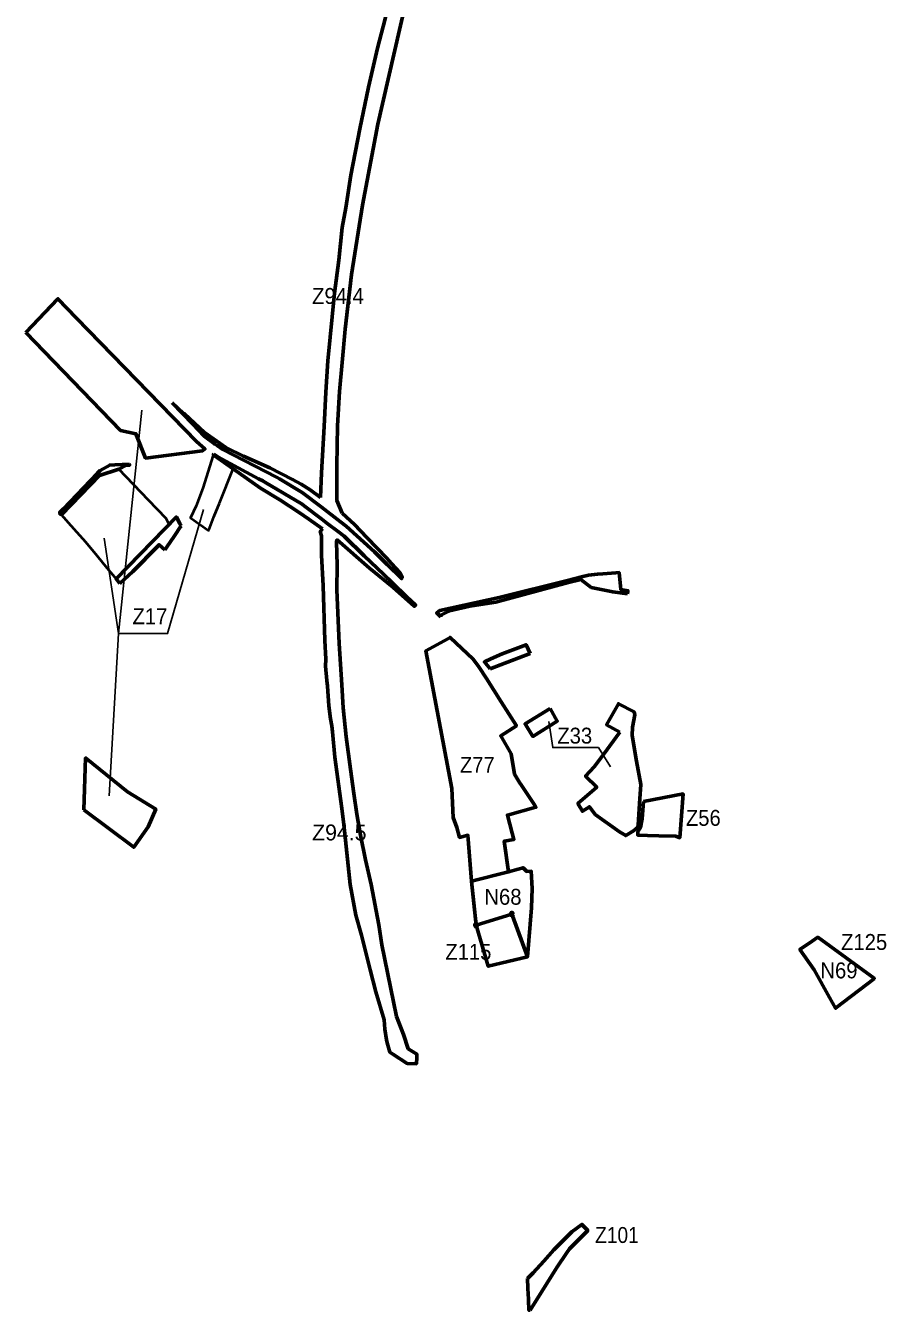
# Model space of a CAD drawing. Extents: x -650277 to -643425, y -1073980 to -1066720.
# Drawn here: x -645817 to -644519, y -1073665 to -1071727 of the extents above; entities that cross this region are included whole.
import ezdxf

# ---------------------------------------------------------------- set-up
doc = ezdxf.new("R2010")
doc.units = 0
doc.header["$LTSCALE"] = 9.6
doc.header["$PDMODE"] = 32
doc.header["$PDSIZE"] = 4.8
for name, color, linetype, lineweight in [('1', 7, 'Continuous', 60), ('15', 7, 'Continuous', 60), ('2', 7, 'Continuous', 40), ('3', 7, 'Continuous', 60), ('42', 7, 'Continuous', 60), ('59', 7, 'Continuous', 25), ('60', 7, 'Continuous', 60), ('63', 7, 'Continuous', 25), ('9', 7, 'Continuous', 60)]:
    doc.layers.add(name, color=color, linetype=linetype, lineweight=lineweight)

msp = doc.modelspace()

# ---------------------------------------------------------------- linework, layer by layer
at = {"layer": '1'}
for points in [[(-645817.219, -1072189.975), (-645768.649, -1072139.283), (-645740.45, -1072168.23), (-645559.34, -1072354.42), (-645546.82, -1072365.72), (-645550.41, -1072368.47), (-645636.37, -1072379.57), (-645650.78, -1072342.73), (-645674, -1072338), (-645789.298, -1072218.833)], [(-645729.36, -1072909.65), (-645654.16, -1072966.3), (-645632.23, -1072935.28), (-645620.92, -1072908.65), (-645663.52, -1072882.58), (-645726.9, -1072831.5)], [(-644536.62, -1073164.33), (-644536.62, -1073164.33), (-644622.03, -1073101.88), (-644622.03, -1073101.88), (-644630.58, -1073107.78), (-644648.95, -1073120.47), (-644627.53, -1073151.26), (-644604.13, -1073193), (-644595.18, -1073208.98)]]:
    msp.add_lwpolyline(points, close=True, dxfattribs=at)
at = {"layer": '15'}
for points in [[(-645708.94, -1072402.11), (-645760.02, -1072455.94), (-645765.95, -1072462.03), (-645763.06, -1072465.26)], [(-645763.06, -1072465.26), (-645706.039, -1072405.769), (-645676.53, -1072396.16)], [(-645661.3, -1072388.74), (-645682.59, -1072389.76), (-645690.37, -1072390.13), (-645705, -1072398.19), (-645708.94, -1072402.11)], [(-645676.53, -1072396.16), (-645676.53, -1072396.16), (-645665.32, -1072390.32), (-645660.16, -1072389.95), (-645661.3, -1072388.74)], [(-645582.84, -1072481.71), (-645584.46, -1072478.58), (-645589.862, -1072468.109), (-645680.87, -1072561.42), (-645675.13, -1072568.36)], [(-645607.07, -1072517.61), (-645605.95, -1072515.95), (-645604.82, -1072514.3), (-645592.9, -1072496.52), (-645583.13, -1072482.13), (-645582.84, -1072481.71)], [(-645675.13, -1072568.36), (-645655.65, -1072550.62), (-645617.87, -1072512.12), (-645615.95, -1072510.16), (-645607.07, -1072517.61)], [(-644926.81, -1072552.51), (-644946.57, -1072554.22), (-644954.57, -1072554.43), (-644967.97, -1072556.17), (-644978.56, -1072558.74), (-644999.72, -1072564.24), (-645102.73, -1072589.74), (-645192.06, -1072609.19), (-645197.044, -1072612.821), (-645190.71, -1072618.6)], [(-644919.75, -1072572.43), (-644921.84, -1072552.03), (-644926.81, -1072552.51)], [(-645147.13, -1072602.79), (-645107.58, -1072596.47), (-644997.92, -1072567.23), (-644979.55, -1072562.44), (-644963.97, -1072574.57)], [(-644963.97, -1072574.57), (-644931.48, -1072581.26), (-644909.02, -1072584.28)], [(-644909.02, -1072584.28), (-644908.59, -1072579.51), (-644919.23, -1072577.46), (-644919.75, -1072572.43)], [(-645190.71, -1072618.6), (-645190.59, -1072616.28), (-645179.6, -1072610.94), (-645177.56, -1072609.89), (-645147.13, -1072602.79)], [(-645056.08, -1072674.07), (-645062.131, -1072660.856), (-645098.016, -1072674.425), (-645115.56, -1072682.406), (-645124.933, -1072686.721), (-645116.11, -1072697.15)], [(-645116.11, -1072697.15), (-645100.9, -1072691.31), (-645056.08, -1072674.07)]]:
    msp.add_lwpolyline(points, dxfattribs=at)
at = {"layer": '2'}
for points in [[(-645503.98, -1072395.64), (-645532.75, -1072375.41), (-645535.05, -1072376.72), (-645549.6, -1072423.39), (-645551.54, -1072428.66), (-645559.92, -1072451.41), (-645568.38, -1072469.68), (-645541.56, -1072488.74), (-645541.09, -1072487.98), (-645533.15, -1072468.21), (-645524.87, -1072447.61)], [(-645600.945, -1072479.473), (-645605.17, -1072470.52), (-645632.1, -1072442.93), (-645632.1, -1072442.93), (-645676.53, -1072396.16), (-645706.039, -1072405.769), (-645763.06, -1072465.26), (-645753.128, -1072476.383), (-645744.38, -1072486.18), (-645726.95, -1072505.7), (-645709.92, -1072526.3), (-645694.51, -1072544.93), (-645680.87, -1072561.42)]]:
    msp.add_lwpolyline(points, close=True, dxfattribs=at)
at = {"layer": '3'}
for points in [[(-644902.18, -1072797.88), (-644901.35, -1072785.36), (-644898.29, -1072766.55), (-644899.2, -1072762.14), (-644922.88, -1072749.97), (-644940.8, -1072781.48), (-644920.46, -1072792.92)], [(-644920.46, -1072792.92), (-644945.2, -1072826.3), (-644959.24, -1072844.92), (-644972.28, -1072859.02), (-644955.49, -1072875.78), (-644983.93, -1072900.24), (-644977.16, -1072912.11), (-644966.57, -1072905.23), (-644957.79, -1072916.73), (-644921.18, -1072943.17), (-644911.87, -1072948.76), (-644900.2, -1072941.67), (-644893.77, -1072935.88), (-644892.86, -1072932.6), (-644891.2, -1072900.09), (-644889.11, -1072871.66), (-644895.32, -1072836.6), (-644902.18, -1072797.88)], [(-645137.5, -1073083.97), (-645119.34, -1073145.61), (-645060.1, -1073131.68), (-645082.6, -1073069.93), (-645083.681, -1073066.962)]]:
    msp.add_lwpolyline(points, dxfattribs=at)
for points in [[(-645025.61, -1072757.17), (-645063.6, -1072780.26), (-645051.94, -1072799.21), (-645015.02, -1072776.01)], [(-645054.12, -1073057.62), (-645052.94, -1073028.58), (-645054.44, -1073002.54), (-645060.95, -1073002.68), (-645066.66, -1072997.3), (-645074.333, -1072999.365), (-645088.62, -1073003.45), (-645144.37, -1073017.64), (-645137.5, -1073083.97), (-645083.681, -1073066.962), (-645082.6, -1073069.93), (-645060.1, -1073131.68)]]:
    msp.add_lwpolyline(points, close=True, dxfattribs=at)
for p in [(-645083.681, -1073066.962), (-645137.5, -1073083.97)]:
    msp.add_point(p, dxfattribs=at)
at = {"layer": '42'}
msp.add_lwpolyline([(-645817.219, -1072189.975), (-645768.649, -1072139.283), (-645740.45, -1072168.23), (-645559.34, -1072354.42), (-645546.82, -1072365.72), (-645550.41, -1072368.47), (-645636.37, -1072379.57), (-645650.78, -1072342.73), (-645674, -1072338), (-645789.298, -1072218.833)], close=True, dxfattribs=at)
at = {"layer": '59'}
for points in [[(-645549, -1072457), (-645603, -1072644), (-645677, -1072644)], [(-645677, -1072644), (-645677, -1072644), (-645699, -1072500)]]:
    msp.add_lwpolyline(points, dxfattribs=at)
at = {"layer": '60'}
for points in [[(-645339.904, -1072462.677), (-645347.551, -1072443.527), (-645347.677, -1072391.355), (-645346.62, -1072330.914), (-645343.458, -1072278.998), (-645339.908, -1072235.158), (-645335.367, -1072185.207), (-645325.498, -1072102.789), (-645309.01, -1071998.147), (-645285.617, -1071875.733), (-645244.798, -1071696.585), (-645235.793, -1071663.703), (-645230.436, -1071634.261), (-645227.905, -1071625.277), (-645222.48, -1071606.08)], [(-645255.662, -1071626.67), (-645261.094, -1071645.025), (-645264.841, -1071657.687), (-645269.077, -1071687.396), (-645274.868, -1071717.176), (-645286.175, -1071761.228), (-645300.076, -1071820.179), (-645313.153, -1071883.081)], [(-645313.153, -1071883.081), (-645326.343, -1071952.807), (-645334.118, -1072001.954), (-645339.455, -1072031.565), (-645344.819, -1072081.225), (-645351.358, -1072130.815), (-645361.317, -1072232.824), (-645364.435, -1072280.268), (-645366.951, -1072331.609), (-645370.624, -1072401.447), (-645372.228, -1072438.764)], [(-645372.228, -1072438.764), (-645387.894, -1072427.453), (-645401.441, -1072419.033), (-645414.631, -1072411.611), (-645448.831, -1072394.325), (-645488.64, -1072376.782), (-645515.437, -1072363.447), (-645547.593, -1072340.827), (-645577.33, -1072312.704), (-645579.217, -1072312.425), (-645596.405, -1072296.114)], [(-645596.405, -1072296.114), (-645564.4, -1072328.61), (-645547.72, -1072346.19), (-645532.07, -1072358.01), (-645531.65, -1072358.29), (-645528.27, -1072360.53), (-645519.57, -1072366.3), (-645438.64, -1072408.1)], [(-645533.08, -1072373.71), (-645534.3, -1072374.33), (-645532.75, -1072375.41), (-645503.98, -1072395.64)], [(-645370.226, -1072471.736), (-645396.94, -1072451.44), (-645400.12, -1072449.03), (-645456.52, -1072415.6), (-645459.31, -1072413.95), (-645465.793, -1072410.498), (-645527.33, -1072377.73), (-645533.08, -1072373.71)], [(-645503.98, -1072395.64), (-645462.65, -1072425.01), (-645462.651, -1072425.011), (-645462.646, -1072425.015)], [(-645462.646, -1072425.015), (-645433.91, -1072442.56), (-645404.64, -1072461.72), (-645389.731, -1072471.612), (-645369.364, -1072485.931)], [(-645438.64, -1072408.1), (-645437.6, -1072408.64), (-645434.19, -1072410.67), (-645399.77, -1072431.12), (-645371.356, -1072453.119), (-645342.284, -1072475.625)], [(-645290.76, -1072520.92), (-645271.74, -1072539.96), (-645249.9, -1072561.25), (-645248.967, -1072559.511), (-645252.768, -1072552.178), (-645265.009, -1072538.358), (-645272.276, -1072530.154), (-645302.303, -1072499.014), (-645320.805, -1072479.495), (-645339.904, -1072462.677)], [(-645345.079, -1072490.836), (-645362.81, -1072477.37), (-645370.226, -1072471.736)], [(-645342.284, -1072475.625), (-645333.62, -1072482.33), (-645290.76, -1072520.92)], [(-645369.364, -1072485.931), (-645372.72, -1072490.314), (-645370.928, -1072496.619), (-645370.755, -1072525.734), (-645368.173, -1072571.881), (-645366.022, -1072654.462), (-645364.524, -1072682.575), (-645364.786, -1072692.977), (-645362.708, -1072714.781)], [(-645338.023, -1072755.969), (-645339.96, -1072721.587), (-645344.152, -1072658.857), (-645347.795, -1072577.893), (-645347.214, -1072540.97), (-645348.253, -1072505.583), (-645347.292, -1072502.877), (-645298.498, -1072545.352)], [(-645242, -1072588.6), (-645263.7, -1072567.8), (-645276.93, -1072555.11), (-645306.46, -1072527.08), (-645336.33, -1072497.48), (-645336.887, -1072497.057), (-645345.079, -1072490.836)], [(-645298.498, -1072545.352), (-645263.217, -1072574.314), (-645230.845, -1072602.888), (-645228.96, -1072600.865), (-645241.87, -1072588.722), (-645242, -1072588.6)], [(-645362.708, -1072714.781), (-645361.874, -1072723.527), (-645359.76, -1072752.865), (-645357.272, -1072772.771), (-645355.121, -1072782.993)], [(-645317.65, -1072916.642), (-645322.284, -1072885.085), (-645327.091, -1072848.387), (-645333.718, -1072799.987), (-645338.023, -1072755.969)], [(-645355.121, -1072782.993), (-645354.019, -1072792.454), (-645350.822, -1072830.388), (-645340.345, -1072908.029), (-645337.34, -1072932.073), (-645332.517, -1072974.538), (-645327.554, -1073022.214)], [(-645304.24, -1072985.372), (-645311.772, -1072947.945), (-645317.65, -1072916.642)], [(-645257.842, -1073221.36), (-645262.388, -1073199.409), (-645279.878, -1073113.356), (-645284.269, -1073083.286), (-645295.788, -1073022.556), (-645304.24, -1072985.372)], [(-645327.554, -1073022.214), (-645319.052, -1073068.6), (-645310.558, -1073098.946), (-645297.395, -1073151.294), (-645288.647, -1073184.518), (-645276.125, -1073226.571), (-645275.269, -1073240.71), (-645272.747, -1073256.762), (-645271.518, -1073261.16), (-645267.525, -1073275.443), (-645263.03, -1073278.25), (-645241.72, -1073292.2), (-645227.744, -1073292.736), (-645227.199, -1073283.366), (-645226.847, -1073278.345), (-645239.9, -1073270.025), (-645247.051, -1073248.736), (-645257.842, -1073221.36)]]:
    msp.add_lwpolyline(points, dxfattribs=at)
at = {"layer": '63'}
for q in [(-645642, -1072307), (-645691, -1072889)]:
    msp.add_line((-645677, -1072644), q, dxfattribs=at)
msp.add_lwpolyline([(-645027.959, -1072776.842), (-645022, -1072816), (-644953, -1072816), (-644935, -1072845)], dxfattribs=at)
at = {"layer": '9'}
for points in [[(-645144.37, -1073017.64), (-645088.62, -1073003.45), (-645095.04, -1072957.07), (-645080.61, -1072954.43), (-645083.13, -1072944.94), (-645090.34, -1072917.86), (-645047.42, -1072906.05), (-645050.6, -1072901.03), (-645069.55, -1072872.12), (-645071.87, -1072868.45), (-645079.81, -1072855.89), (-645084.47, -1072825.67), (-645100.27, -1072798.46), (-645076.66, -1072783.06), (-645099.58, -1072746.945), (-645121.96, -1072711.68), (-645133.26, -1072694.17), (-645142.1, -1072682.57), (-645176.757, -1072649.968), (-645180.05, -1072651.77), (-645213.34, -1072669.98), (-645174.13, -1072877.93), (-645172.28, -1072921.42), (-645166.48, -1072936.5), (-645162.379, -1072951.55), (-645149.84, -1072948.13)], [(-644884.94, -1072897.19), (-644886.98, -1072923.48), (-644889.65, -1072936.67), (-644893.37, -1072942.61), (-644893.59, -1072947.97), (-644878.86, -1072948.42), (-644861.93, -1072948.94), (-644835.99, -1072949.74), (-644830.25, -1072951.9), (-644825.25, -1072885.96)]]:
    msp.add_lwpolyline(points, close=True, dxfattribs=at)
for points in [[(-645056.06, -1073664.2), (-645043.35, -1073644.04), (-645015.55, -1073599.96), (-645001.267, -1073578.582), (-644996.41, -1073571.97), (-644985.66, -1073560.69), (-644969.117, -1073544.254), (-644977.924, -1073535.072), (-644993.044, -1073546.324), (-645020.11, -1073573.585), (-645035.303, -1073590.199), (-645051.513, -1073608.124), (-645060.009, -1073616.53)], [(-645060.009, -1073616.53), (-645059.35, -1073631.3), (-645058.96, -1073640.09), (-645058.65, -1073647), (-645058.42, -1073652.18), (-645058.01, -1073661.37), (-645057.87, -1073664.55), (-645056.06, -1073664.2)]]:
    msp.add_lwpolyline(points, dxfattribs=at)

# ---------------------------------------------------------------- texts
at = {"layer": '59', "width": 0.95}
msp.add_text('Z17', height=24, dxfattribs=at).set_placement((-645656, -1072630))
at = {"layer": '63'}
for s, width, p in [('Z94.4', 0.95, (-645385, -1072147)), ('Z33', 0.95, (-645015, -1072810)), ('Z77', 0.95, (-645162, -1072854)), ('Z56', 0.95, (-644821, -1072934)), ('N68', 0.95, (-645125, -1073053)), ('Z125', 0.95, (-644586.786, -1073121.127)), ('Z115', 0.95, (-645184, -1073136)), ('N69', 0.95, (-644618, -1073164)), ('Z101', 0.9, (-644958, -1073563))]:
    msp.add_text(s, height=24, dxfattribs=dict(at, width=width)).set_placement(p)
msp.add_text('Z94.5', height=24, dxfattribs=at).set_placement((-645385, -1072956))

doc.saveas('drawing.dxf')
